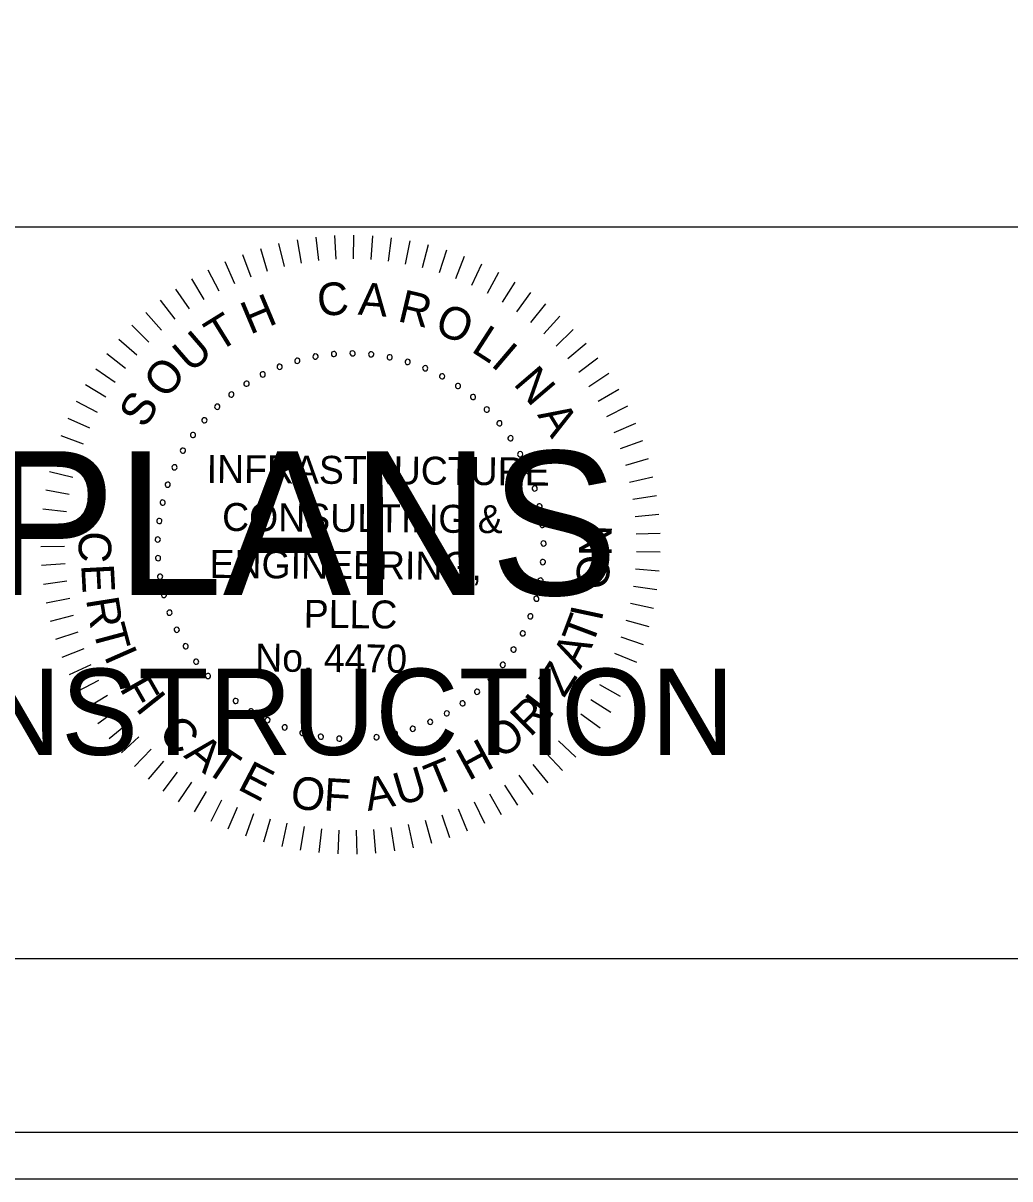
# Model space of a CAD drawing. Extents: x 967 to 1326, y 964 to 3144.
# Drawn here: x 1189.3 to 1212.88, y 2923.72 to 2951.36 of the extents above; entities that cross this region are included whole.
import ezdxf

# ---------------------------------------------------------------- set-up
doc = ezdxf.new("R2010")
doc.units = 0
for name, color, linetype in [('RD_XS_EwShp', 7, 'Continuous'), ('RD_XS_ExPaveRet', 7, 'Continuous'), ('RD_XS_TX_Elev_EX', 7, 'Continuous'), ('RD_XS_TX_Elev_PR', 7, 'Continuous'), ('RD_XS_TX_Station', 7, 'Continuous')]:
    doc.layers.add(name, color=color, linetype=linetype)

msp = doc.modelspace()

# ---------------------------------------------------------------- linework, layer by layer
at = {"layer": 'RD_XS_ExPaveRet'}
for points in [[(967.409, 2923.72), (1326.285, 2923.72), (1326.285, 3143.72), (967.409, 3143.72)], [(988.525, 2924.84), (1326.285, 2924.84), (1326.285, 3142.6), (988.525, 3142.6)]]:
    msp.add_lwpolyline(points, close=True, dxfattribs=at)
at = {"layer": 'RD_XS_TX_Elev_EX'}
for p, q in [((996.114, 2946.486), (1323.886, 2946.486)), ((1323.886, 2928.983), (996.114, 2928.983))]:
    msp.add_line(p, q, dxfattribs=at)
at = {"layer": 'RD_XS_TX_Elev_PR'}
for p, q in [((1195.846, 2946.181), (1195.945, 2945.62)), ((1196.292, 2946.245), (1196.357, 2945.68)), ((1196.742, 2946.282), (1196.772, 2945.714)), ((1197.194, 2946.292), (1197.189, 2945.723)), ((1197.645, 2946.274), (1197.606, 2945.706)), ((1198.094, 2946.228), (1198.02, 2945.664)), ((1198.54, 2946.156), (1198.432, 2945.596)), ((1194.968, 2945.971), (1195.134, 2945.427)), ((1195.403, 2946.09), (1195.536, 2945.536)), ((1198.98, 2946.056), (1198.838, 2945.504)), ((1199.414, 2945.929), (1199.238, 2945.387)), ((1194.122, 2945.656), (1194.353, 2945.136)), ((1194.54, 2945.827), (1194.739, 2945.293)), ((1199.839, 2945.777), (1199.63, 2945.246)), ((1200.253, 2945.598), (1200.013, 2945.082)), ((1193.715, 2945.461), (1193.978, 2944.956)), ((1200.656, 2945.395), (1200.385, 2944.894)), ((1193.321, 2945.241), (1193.614, 2944.752)), ((1201.047, 2945.167), (1200.745, 2944.684)), ((1192.94, 2944.997), (1193.263, 2944.528)), ((1201.422, 2944.917), (1201.092, 2944.453)), ((1192.576, 2944.731), (1192.926, 2944.282)), ((1201.781, 2944.643), (1201.424, 2944.2)), ((1192.228, 2944.443), (1192.605, 2944.016)), ((1202.124, 2944.349), (1201.739, 2943.928)), ((1191.899, 2944.134), (1192.301, 2943.731)), ((1202.447, 2944.034), (1202.038, 2943.638)), ((1191.589, 2943.805), (1192.015, 2943.428)), ((1202.751, 2943.7), (1202.318, 2943.329)), ((1191.299, 2943.459), (1191.748, 2943.108)), ((1191.032, 2943.095), (1191.501, 2942.772)), ((1203.034, 2943.348), (1202.579, 2943.004)), ((1203.294, 2942.979), (1202.82, 2942.664)), ((1190.787, 2942.716), (1191.274, 2942.422)), ((1203.532, 2942.595), (1203.04, 2942.31)), ((1190.565, 2942.323), (1191.07, 2942.059)), ((1203.746, 2942.198), (1203.237, 2941.943)), ((1190.368, 2941.916), (1190.888, 2941.684)), ((1203.936, 2941.788), (1203.412, 2941.564)), ((1190.196, 2941.499), (1190.729, 2941.299)), ((1204.1, 2941.367), (1203.563, 2941.176)), ((1190.05, 2941.072), (1190.594, 2940.905)), ((1204.238, 2940.937), (1203.691, 2940.779)), ((1189.93, 2940.636), (1190.484, 2940.503)), ((1204.349, 2940.5), (1203.794, 2940.375)), ((1189.837, 2940.195), (1190.398, 2940.095)), ((1204.434, 2940.056), (1203.872, 2939.966)), ((1189.771, 2939.748), (1190.337, 2939.683)), ((1204.491, 2939.608), (1203.925, 2939.552)), ((1189.732, 2939.298), (1190.301, 2939.267)), ((1204.522, 2939.158), (1203.953, 2939.137)), ((1189.721, 2938.847), (1190.29, 2938.851)), ((1204.524, 2938.706), (1203.955, 2938.72)), ((1189.737, 2938.396), (1190.306, 2938.434)), ((1204.499, 2938.256), (1203.932, 2938.304)), ((1189.781, 2937.946), (1190.346, 2938.019)), ((1204.447, 2937.807), (1203.884, 2937.89)), ((1189.852, 2937.5), (1190.412, 2937.608)), ((1204.367, 2937.363), (1203.81, 2937.479)), ((1189.951, 2937.06), (1190.502, 2937.201)), ((1204.261, 2936.924), (1203.712, 2937.074)), ((1190.076, 2936.626), (1190.617, 2936.8)), ((1204.128, 2936.492), (1203.589, 2936.676)), ((1190.227, 2936.2), (1190.757, 2936.408)), ((1203.969, 2936.07), (1203.442, 2936.286)), ((1190.403, 2935.785), (1190.92, 2936.024)), ((1203.784, 2935.658), (1203.271, 2935.906)), ((1190.605, 2935.381), (1191.106, 2935.651)), ((1203.574, 2935.258), (1203.078, 2935.537)), ((1190.831, 2934.99), (1191.315, 2935.291)), ((1203.341, 2934.871), (1202.862, 2935.18)), ((1191.081, 2934.614), (1191.545, 2934.943)), ((1203.085, 2934.5), (1202.626, 2934.837)), ((1191.353, 2934.253), (1191.796, 2934.61)), ((1191.646, 2933.91), (1192.067, 2934.293)), ((1202.806, 2934.145), (1202.368, 2934.509)), ((1191.96, 2933.585), (1192.356, 2933.994)), ((1202.506, 2933.807), (1202.092, 2934.197)), ((1192.293, 2933.28), (1192.664, 2933.712)), ((1202.186, 2933.488), (1201.796, 2933.903)), ((1192.644, 2932.996), (1192.988, 2933.45)), ((1201.847, 2933.19), (1201.484, 2933.628)), ((1193.011, 2932.734), (1193.327, 2933.208)), ((1201.119, 2932.657), (1200.811, 2933.136)), ((1201.491, 2932.912), (1201.155, 2933.372)), ((1193.394, 2932.495), (1193.68, 2932.987)), ((1200.731, 2932.425), (1200.453, 2932.922)), ((1193.791, 2932.279), (1194.047, 2932.788)), ((1194.2, 2932.088), (1194.424, 2932.612)), ((1200.331, 2932.217), (1200.083, 2932.73)), ((1194.62, 2931.923), (1194.812, 2932.459)), ((1195.05, 2931.783), (1195.208, 2932.33)), ((1199.495, 2931.877), (1199.312, 2932.416)), ((1199.918, 2932.034), (1199.702, 2932.561)), ((1195.487, 2931.67), (1195.612, 2932.225)), ((1195.93, 2931.584), (1196.021, 2932.146)), ((1196.377, 2931.524), (1196.434, 2932.091)), ((1196.828, 2931.493), (1196.85, 2932.062)), ((1197.279, 2931.488), (1197.267, 2932.058)), ((1197.73, 2931.512), (1197.683, 2932.079)), ((1198.179, 2931.562), (1198.097, 2932.126)), ((1198.624, 2931.64), (1198.508, 2932.198)), ((1199.063, 2931.745), (1198.913, 2932.295))]:
    msp.add_line(p, q, dxfattribs=at)
for centre, start, end in [((1196.285, 2943.388), 10.6038, 190.6038), ((1196.285, 2943.388), 190.6038, 10.6038), ((1196.727, 2943.447), 5.0653, 185.0653), ((1196.727, 2943.447), 185.0653, 5.0653), ((1197.172, 2943.464), 359.5268, 179.5268), ((1197.172, 2943.464), 179.5268, 359.5268), ((1197.617, 2943.438), 173.9884, 353.9884), ((1197.617, 2943.438), 353.9884, 173.9884), ((1198.057, 2943.369), 168.4499, 348.4499), ((1198.057, 2943.369), 348.4499, 168.4499), ((1195.429, 2943.142), 21.6807, 201.6807), ((1195.429, 2943.142), 201.6807, 21.6807), ((1195.851, 2943.285), 16.1422, 196.1422), ((1195.851, 2943.285), 196.1422, 16.1422), ((1198.489, 2943.258), 162.9114, 342.9114), ((1198.489, 2943.258), 342.9114, 162.9114), ((1198.908, 2943.106), 157.373, 337.373), ((1198.908, 2943.106), 337.373, 157.373), ((1195.023, 2942.958), 27.2191, 207.2191), ((1195.023, 2942.958), 207.2191, 27.2191), ((1199.31, 2942.914), 151.8345, 331.8345), ((1199.31, 2942.914), 331.8345, 151.8345), ((1194.274, 2942.478), 38.2961, 218.2961), ((1194.637, 2942.736), 32.7576, 212.7576), ((1194.637, 2942.736), 212.7576, 32.7576), ((1199.692, 2942.684), 146.2961, 326.2961), ((1199.692, 2942.684), 326.2961, 146.2961), ((1194.274, 2942.478), 218.2961, 38.2961), ((1200.05, 2942.419), 140.7576, 320.7576), ((1200.05, 2942.419), 320.7576, 140.7576), ((1193.937, 2942.186), 43.8345, 223.8345), ((1193.937, 2942.186), 223.8345, 43.8345), ((1200.38, 2942.12), 135.2191, 315.2191), ((1200.38, 2942.12), 315.2191, 135.2191), ((1193.63, 2941.862), 49.373, 229.373), ((1193.63, 2941.862), 229.373, 49.373), ((1200.68, 2941.79), 129.6807, 309.6807), ((1200.68, 2941.79), 309.6807, 129.6807), ((1193.356, 2941.511), 54.9114, 234.9114), ((1193.356, 2941.511), 234.9114, 54.9114), ((1200.947, 2941.433), 124.1422, 304.1422), ((1200.947, 2941.433), 304.1422, 124.1422), ((1193.117, 2941.135), 60.4499, 240.4499), ((1193.117, 2941.135), 240.4499, 60.4499), ((1201.179, 2941.052), 118.6038, 298.6038), ((1201.179, 2941.052), 298.6038, 118.6038), ((1192.915, 2940.737), 65.9884, 245.9884), ((1192.915, 2940.737), 245.9884, 65.9884), ((1201.372, 2940.651), 113.0653, 293.0653), ((1201.372, 2940.651), 293.0653, 113.0653), ((1192.753, 2940.322), 71.5268, 251.5268), ((1192.753, 2940.322), 251.5268, 71.5268), ((1201.526, 2940.233), 107.5268, 287.5268), ((1201.526, 2940.233), 287.5268, 107.5268), ((1192.632, 2939.894), 77.0653, 257.0653), ((1192.632, 2939.894), 257.0653, 77.0653), ((1201.638, 2939.801), 101.9884, 281.9884), ((1201.638, 2939.801), 281.9884, 101.9884), ((1192.552, 2939.455), 82.6038, 262.6038), ((1192.552, 2939.455), 262.6038, 82.6038), ((1201.709, 2939.361), 96.4499, 276.4499), ((1201.709, 2939.361), 276.4499, 96.4499), ((1192.515, 2939.011), 88.1422, 268.1422), ((1192.515, 2939.011), 268.1422, 88.1422), ((1201.737, 2938.917), 90.9114, 270.9114), ((1201.737, 2938.917), 270.9114, 90.9114), ((1192.522, 2938.565), 93.6807, 273.6807), ((1192.522, 2938.565), 273.6807, 93.6807), ((1201.721, 2938.471), 85.373, 265.373), ((1201.721, 2938.471), 265.373, 85.373), ((1192.571, 2938.122), 99.2191, 279.2191), ((1192.571, 2938.122), 279.2191, 99.2191), ((1201.663, 2938.029), 79.8345, 259.8345), ((1201.663, 2938.029), 259.8345, 79.8345), ((1192.662, 2937.686), 104.7576, 284.7576), ((1192.662, 2937.686), 284.7576, 104.7576), ((1201.563, 2937.595), 74.2961, 254.2961), ((1201.563, 2937.595), 254.2961, 74.2961), ((1192.796, 2937.261), 110.2961, 290.2961), ((1192.796, 2937.261), 290.2961, 110.2961), ((1201.42, 2937.173), 68.7576, 248.7576), ((1201.42, 2937.173), 248.7576, 68.7576), ((1192.97, 2936.851), 115.8345, 295.8345), ((1192.97, 2936.851), 295.8345, 115.8345), ((1201.238, 2936.766), 63.2191, 243.2191), ((1201.238, 2936.766), 243.2191, 63.2191), ((1193.182, 2936.459), 121.373, 301.373), ((1193.182, 2936.459), 301.373, 121.373), ((1201.018, 2936.379), 57.6807, 237.6807), ((1201.018, 2936.379), 237.6807, 57.6807), ((1193.432, 2936.09), 126.9114, 306.9114), ((1193.432, 2936.09), 306.9114, 126.9114), ((1200.761, 2936.014), 52.1422, 232.1422), ((1200.761, 2936.014), 232.1422, 52.1422), ((1193.715, 2935.746), 132.4499, 312.4499), ((1193.715, 2935.746), 312.4499, 132.4499), ((1200.47, 2935.677), 46.6038, 226.6038), ((1200.47, 2935.677), 226.6038, 46.6038), ((1194.031, 2935.431), 137.9884, 317.9884), ((1194.031, 2935.431), 317.9884, 137.9884), ((1200.148, 2935.369), 41.0653, 221.0653), ((1200.148, 2935.369), 221.0653, 41.0653), ((1194.376, 2935.149), 143.5268, 323.5268), ((1194.376, 2935.149), 323.5268, 143.5268), ((1199.798, 2935.093), 35.5268, 215.5268), ((1199.798, 2935.093), 215.5268, 35.5268), ((1194.746, 2934.901), 149.0653, 329.0653), ((1194.746, 2934.901), 329.0653, 149.0653), ((1199.422, 2934.853), 29.9884, 209.9884), ((1199.422, 2934.853), 209.9884, 29.9884), ((1195.139, 2934.69), 154.6038, 334.6038), ((1195.139, 2934.69), 334.6038, 154.6038), ((1195.55, 2934.517), 160.1422, 340.1422), ((1195.55, 2934.517), 340.1422, 160.1422), ((1198.611, 2934.486), 18.9114, 198.9114), ((1199.026, 2934.65), 24.4499, 204.4499), ((1199.026, 2934.65), 204.4499, 24.4499), ((1195.975, 2934.386), 165.6807, 345.6807), ((1195.975, 2934.386), 345.6807, 165.6807), ((1196.412, 2934.295), 171.2191, 351.2191), ((1196.412, 2934.295), 351.2191, 171.2191), ((1196.855, 2934.248), 356.7576, 176.7576), ((1196.855, 2934.248), 176.7576, 356.7576), ((1197.301, 2934.243), 2.2961, 182.2961), ((1197.301, 2934.243), 182.2961, 2.2961), ((1197.745, 2934.282), 7.8345, 187.8345), ((1197.745, 2934.282), 187.8345, 7.8345), ((1198.183, 2934.363), 13.373, 193.373), ((1198.183, 2934.363), 193.373, 13.373), ((1198.611, 2934.486), 198.9114, 18.9114)]:
    msp.add_arc(centre, 0.0627, start, end, dxfattribs=at)
at = {"layer": 'RD_XS_TX_Station'}
msp.add_lwpolyline([(967.409, 2923.72), (1326.285, 2923.72), (1326.285, 3143.72), (967.409, 3143.72)], close=True, dxfattribs=at)

# ---------------------------------------------------------------- texts
at = {"layer": 'RD_XS_EwShp'}
for s, height, p in [('FINAL PLANS', 3.4375, (1174.145, 2937.685)), ('NOT FOR CONSTRUCTION', 2.0625, (1170.901, 2933.86))]:
    msp.add_text(s, height=height, dxfattribs=at).set_placement(p)
at = {"layer": 'RD_XS_TX_Elev_PR'}
for s, height, rotation, p in [('C', 0.78, 4.7281, (1196.355, 2944.346)), ('A', 0.78, 355.6981, (1197.29, 2944.39)), ('H', 0.78, 22.7882, (1194.72, 2943.904)), ('R', 0.78, 346.6681, (1198.222, 2944.238)), ('T', 0.78, 31.8182, (1193.961, 2943.478)), ('O', 0.78, 337.638, (1199.096, 2943.972)), ('U', 0.78, 40.8482, (1193.306, 2942.976)), ('L', 0.78, 327.108, (1199.981, 2943.52)), ('I', 0.78, 319.578, (1200.451, 2943.182)), ('O', 0.78, 49.8782, (1192.707, 2942.341)), ('N', 0.78, 310.548, (1200.994, 2942.728)), ('S', 0.78, 58.9083, (1192.211, 2941.642)), ('A', 0.78, 301.5179, (1201.576, 2941.991)), ('INFRASTRUCTURE', 0.66873, 359.5268, (1193.682, 2940.367)), ('CONSULTING &', 0.66873, 359.5268, (1194.051, 2939.217)), ('N', 0.78, 89.2085, (1203.359, 2938.604)), ('C', 0.78, 267.025, (1190.646, 2939.227)), ('ENGINEERING,', 0.66873, 359.5268, (1193.751, 2938.095)), ('O', 0.78, 83.2085, (1203.26, 2937.786)), ('E', 0.78, 273.025, (1190.685, 2938.408)), ('R', 0.78, 279.025, (1190.799, 2937.583)), ('PLLC', 0.6687, 359.5268, (1196.002, 2936.9)), ('I', 0.78, 77.9093, (1203.121, 2937.032)), ('T', 0.78, 285.025, (1190.955, 2936.878)), ('T', 0.78, 69.3954, (1202.891, 2936.428)), ('I', 0.78, 293.7713, (1191.221, 2936.225)), ('No. 4470', 0.6687, 359.5268, (1194.843, 2935.855)), ('A', 0.78, 63.3954, (1202.616, 2935.888)), ('Z', 0.78, 57.3954, (1202.224, 2935.206)), ('F', 0.78, 299.7713, (1191.589, 2935.455)), ('I', 0.78, 308.5268, (1191.965, 2934.973)), ('R', 0.78, 44.5268, (1201.415, 2934.267)), ('I', 0.78, 52.3339, (1201.856, 2934.69)), ('C', 0.78, 314.5268, (1192.496, 2934.346)), ('O', 0.78, 38.5268, (1200.73, 2933.731)), ('A', 0.78, 320.5268, (1193.115, 2933.822)), ('T', 0.78, 326.5268, (1193.602, 2933.478)), ('H', 0.78, 28.5268, (1199.942, 2933.23)), ('E', 0.78, 332.5268, (1194.394, 2933.051)), ('T', 0.78, 22.5268, (1199.108, 2932.856)), ('U', 0.78, 16.5268, (1198.288, 2932.638)), ('O', 0.78, 350.5268, (1195.647, 2932.614)), ('F', 0.78, 356.5268, (1196.465, 2932.532)), ('A', 0.78, 10.5268, (1197.537, 2932.517))]:
    msp.add_text(s, height=height, rotation=rotation, dxfattribs=at).set_placement(p)

doc.saveas('drawing.dxf')
